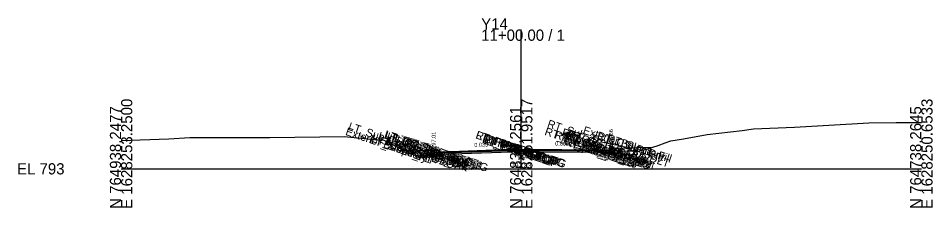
# Model space of a CAD drawing. Extents: x -26 to 1403, y -10 to 4517.
# Drawn here: x -25.7 to 202.8, y 1990.3 to 2037.5 of the extents above; entities that cross this region are included whole.
import ezdxf

# ---------------------------------------------------------------- set-up
doc = ezdxf.new("R2010")
doc.units = 0
for name, color, linetype in [('Default', 7, 'Continuous'), ('Exist CMT Pavement', 7, 'Continuous'), ('Exist Cross Section Cell', 7, 'Continuous'), ('Exist XS Center Line Elevation Label', 7, 'Continuous'), ('Exist XS Ground Line', 7, 'Continuous'), ('Prop CMT Conc Surface', 7, 'Continuous'), ('Prop CMT Concrete Structures', 7, 'Continuous'), ('Prop CMT Pvmt Course 1', 7, 'Continuous'), ('Prop CMT Pvmt Course 1 CG', 7, 'Continuous'), ('Prop CMT Pvmt Course 1 Wedge', 7, 'Continuous'), ('Prop CMT Pvmt Course 2', 7, 'Continuous'), ('Prop CMT Pvmt Course 2 Wedge', 7, 'Continuous'), ('Prop CMT Pvmt Course 3', 7, 'Continuous'), ('Prop CMT Pvmt Course 3 Wedge', 7, 'Continuous'), ('Prop CMT Pvmt Surface', 7, 'Continuous'), ('Prop CMT Pvmt Wedge Surface 1', 7, 'Continuous'), ('Prop CMT Pvmt Wedge Surface 2', 7, 'Continuous'), ('Prop CMT Pvmt Wedge Surface 3', 7, 'Continuous'), ('Prop CMT Slope Grass', 7, 'Continuous'), ('Prop CMT Subgrade Earthwork', 7, 'Continuous'), ('Prop XS Hydro Elevations', 7, 'Continuous'), ('Prop XS SE Text', 7, 'Continuous'), ('Scratch_Level_0', 7, 'Continuous')]:
    doc.layers.add(name, color=color, linetype=linetype)

msp = doc.modelspace()

# ---------------------------------------------------------------- linework, layer by layer
at = {"layer": 'Exist CMT Pavement'}
for points in [[(100, 2004.83), (96.42, 2004.84), (91.88, 2004.58), (80.18, 2003.95)], [(100, 2004.83), (80.18, 2003.95)], [(100, 2004.83), (104.2, 2004.83), (120.36, 2004.67)], [(100, 2004.83), (120.36, 2004.67)], [(120.36, 2004.67), (120.36, 2004.67)], [(80.18, 2003.95), (80.18, 2003.95)]]:
    msp.add_lwpolyline(points, dxfattribs=at)
at = {"layer": 'Exist Cross Section Cell'}
for p, q in [((100, 2000), (100, 2034.73)), ((0, 2000), (100, 2000)), ((100, 2000), (200, 2000))]:
    msp.add_line(p, q, dxfattribs=at)
at = {"layer": 'Exist XS Ground Line'}
msp.add_lwpolyline([(0, 2007.07), (11.97, 2007.49), (17.14, 2007.8), (31.71, 2007.81), (37.14, 2007.78), (49.67, 2007.98), (55.72, 2008.05), (64.16, 2007.23), (65.65, 2007.16), (67.35, 2006.31), (73.65, 2003.27), (75.02, 2003.31), (80.18, 2003.95), (91.88, 2004.58), (96.42, 2004.84), (100, 2004.83), (104.2, 2004.83), (120.36, 2004.67), (124.91, 2004.47), (129.26, 2004.42), (131.35, 2004.89), (134.23, 2005.81), (135.97, 2006.48), (137.35, 2006.96), (140.57, 2007.5), (146.51, 2008.53), (155.21, 2009.58), (158.09, 2009.99), (168.31, 2010.4), (186.85, 2011.47), (193.67, 2011.54), (200, 2011.58)], dxfattribs=at)
at = {"layer": 'Prop CMT Conc Surface'}
for points in [[(78.12, 2004.01), (78.11, 2004.51), (77.61, 2004.51)], [(120.43, 2004.75), (122.43, 2004.66)], [(122.43, 2004.66), (122.43, 2005.16), (122.93, 2005.16)], [(80.12, 2004.16), (78.12, 2004.01)]]:
    msp.add_lwpolyline(points, dxfattribs=at)
at = {"layer": 'Prop CMT Concrete Structures'}
for points in [[(80.12, 2004.16), (78.12, 2004.01), (78.11, 2004.51), (77.61, 2004.51)], [(77.61, 2004.51), (77.62, 2003.49), (80.12, 2003.58)], [(120.43, 2004.75), (122.43, 2004.66), (122.43, 2005.16), (122.93, 2005.16)], [(122.93, 2005.16), (122.93, 2004.16), (120.43, 2004.17)], [(120.43, 2004.17), (120.43, 2004.75)], [(80.12, 2003.58), (80.12, 2004.16)]]:
    msp.add_lwpolyline(points, dxfattribs=at)
at = {"layer": 'Prop CMT Pvmt Course 1'}
for points in [[(100, 2004.86), (80.12, 2004.16)], [(80.18, 2004.04), (100, 2004.73)], [(100, 2004.6), (100, 2004.86)], [(100, 2004.86), (120.43, 2004.75)], [(100, 2004.6), (100, 2004.86)], [(100, 2004.73), (100, 2004.6), (100, 2004.6)], [(120.36, 2004.63), (100, 2004.73)], [(100, 2004.73), (100, 2004.6), (100, 2004.6)], [(120.36, 2004.5), (120.36, 2004.63)], [(120.43, 2004.5), (120.36, 2004.5)], [(120.43, 2004.75), (120.43, 2004.5)], [(80.12, 2004.16), (80.12, 2003.91)], [(80.12, 2003.91), (80.18, 2003.91)], [(80.18, 2003.91), (80.18, 2004.04)]]:
    msp.add_lwpolyline(points, dxfattribs=at)
at = {"layer": 'Prop CMT Pvmt Course 1 CG'}
for points in [[(80.12, 2003.58), (77.12, 2003.47), (76.77, 2003.13)], [(76.77, 2003.13), (80.12, 2003.24)], [(80.12, 2003.24), (80.12, 2003.58)], [(120.43, 2004.17), (123.43, 2004.15), (123.76, 2003.82)], [(120.43, 2003.84), (120.43, 2004.17)], [(123.76, 2003.82), (120.43, 2003.84)]]:
    msp.add_lwpolyline(points, dxfattribs=at)
at = {"layer": 'Prop CMT Pvmt Course 1 Wedge'}
for points in [[(100, 2004.73), (80.18, 2004.04)], [(100, 2004.73), (120.36, 2004.63)]]:
    msp.add_lwpolyline(points, dxfattribs=at)
at = {"layer": 'Prop CMT Pvmt Course 2'}
for points in [[(120.36, 2004.17), (120.36, 2004.5)], [(120.36, 2004.5), (120.43, 2004.5)], [(120.43, 2004.5), (120.43, 2004.17)], [(80.18, 2003.91), (80.12, 2003.91)], [(80.12, 2003.91), (80.12, 2003.58)], [(80.12, 2003.58), (80.18, 2003.58)], [(80.18, 2003.58), (80.18, 2003.91)], [(120.43, 2004.17), (120.36, 2004.17)]]:
    msp.add_lwpolyline(points, dxfattribs=at)
at = {"layer": 'Prop CMT Pvmt Course 2 Wedge'}
for points in [[(100, 2004.6), (80.18, 2003.91)], [(100, 2004.6), (120.36, 2004.5)]]:
    msp.add_lwpolyline(points, dxfattribs=at)
at = {"layer": 'Prop CMT Pvmt Course 3'}
for points in [[(80.18, 2003.58), (80.12, 2003.58)], [(80.12, 2003.58), (80.12, 2003.24)], [(80.12, 2003.24), (80.18, 2003.24)], [(80.18, 2003.24), (80.18, 2003.58)], [(120.36, 2004.17), (120.43, 2004.17)], [(120.36, 2003.84), (120.36, 2004.17)], [(120.43, 2003.84), (120.36, 2003.84)], [(120.43, 2004.17), (120.43, 2003.84)]]:
    msp.add_lwpolyline(points, dxfattribs=at)
at = {"layer": 'Prop CMT Pvmt Course 3 Wedge'}
for points in [[(100, 2004.27), (80.18, 2003.58)], [(100, 2004.27), (120.36, 2004.17)]]:
    msp.add_lwpolyline(points, dxfattribs=at)
at = {"layer": 'Prop CMT Pvmt Surface'}
for points in [[(100, 2004.86), (80.12, 2004.16)], [(100, 2004.86), (120.43, 2004.75)]]:
    msp.add_lwpolyline(points, dxfattribs=at)
at = {"layer": 'Prop CMT Pvmt Wedge Surface 1'}
for points in [[(100, 2004.73), (80.18, 2004.04)], [(100, 2004.73), (120.36, 2004.63)], [(120.36, 2004.63), (120.36, 2004.5)], [(120.36, 2004.5), (120.43, 2004.5)], [(120.43, 2004.5), (120.43, 2004.75)], [(80.12, 2003.91), (80.12, 2004.16)], [(80.18, 2003.91), (80.12, 2003.91)], [(80.18, 2004.04), (80.18, 2003.91)]]:
    msp.add_lwpolyline(points, dxfattribs=at)
at = {"layer": 'Prop CMT Pvmt Wedge Surface 2'}
for points in [[(100, 2004.6), (80.12, 2003.91)], [(100, 2004.6), (120.43, 2004.5)], [(120.43, 2004.5), (120.43, 2004.75)], [(80.12, 2003.91), (80.12, 2004.16)]]:
    msp.add_lwpolyline(points, dxfattribs=at)
at = {"layer": 'Prop CMT Pvmt Wedge Surface 3'}
for points in [[(100, 2004.27), (80.12, 2003.58)], [(100, 2004.27), (120.43, 2004.17)], [(120.43, 2004.17), (120.43, 2004.75)], [(80.12, 2003.58), (80.12, 2004.16)]]:
    msp.add_lwpolyline(points, dxfattribs=at)
at = {"layer": 'Prop CMT Slope Grass'}
for points in [[(77.61, 2004.51), (70.8, 2004.65)], [(122.93, 2005.16), (132.82, 2005.36)]]:
    msp.add_lwpolyline(points, dxfattribs=at)
at = {"layer": 'Prop CMT Subgrade Earthwork'}
for points in [[(80.12, 2003.24), (76.77, 2003.13), (75.34, 2004.55)], [(120.36, 2003.84), (120.34, 2004.67)], [(120.43, 2003.84), (123.76, 2003.82), (125.15, 2005.21)], [(80.18, 2003.24), (80.12, 2003.24)], [(80.18, 2003.24), (80.2, 2003.95)], [(120.36, 2003.84), (120.43, 2003.84)]]:
    msp.add_lwpolyline(points, dxfattribs=at)

# ---------------------------------------------------------------- texts
at = {"layer": 'Default'}
msp.add_text('-', height=0.0001, dxfattribs=at).set_placement((0, 2000))
at = {"layer": 'Exist Cross Section Cell'}
for s, p in [('Y14', (90, 2034.73)), ('11+00.00 / 1', (90, 2031.93)), ('EL 793', (-26, 1998.6))]:
    msp.add_text(s, height=2.8, dxfattribs=at).set_placement(p)
for s, p in [('E 1628253.2500', (2.8, 1990)), ('E 1628251.9517', (102.8, 1990)), ('E 1628250.6533', (202.8, 1990)), ('N 764938.2477', (0, 1990)), ('N 764838.2561', (100, 1990)), ('N 764738.2645', (200, 1990))]:
    msp.add_text(s, height=2.8, rotation=90, dxfattribs=at).set_placement(p)
at = {"layer": 'Exist XS Center Line Elevation Label'}
msp.add_text('797.83', height=1.2, dxfattribs=at).set_placement((97.48, 2000.23))
at = {"layer": 'Prop XS Hydro Elevations'}
for s, p in [('797.01', (78.62, 2005.01)), ('797.66', (122.93, 2005.66))]:
    msp.add_text(s, height=1, rotation=90, dxfattribs=at).set_placement(p)
at = {"layer": 'Prop XS SE Text'}
for s, rotation, p in [('0.035', 2.0045, (88.29, 2005.45)), ('0.005', 359.7135, (108.48, 2005.81))]:
    msp.add_text(s, height=1, rotation=rotation, dxfattribs=at).set_placement(p)
at = {"layer": 'Scratch_Level_0'}
for s, p in [('LT_Sub_Trench_Out_DLT', (56.59, 2009.75)), ('RT_Sub_Trench_Out_DLT', (106.35, 2010.42)), ('Exterior Boundary', (55.92, 2008.48)), ('LT_PV_Sub_Tie_Out', (65.6, 2007.76)), ('LT_CG_Top_Face', (65.71, 2007.59)), ('LT_CG_Top_BOC', (66.18, 2007.27)), ('RT_PV_IEEOP_EG', (88.43, 2007.63)), ('LT_PV_IEEOP_EG', (88.48, 2007.62)), ('RT_PV_Sub_Tie_Out', (105.7, 2008.49)), ('RT_PV_OEEOP_EG', (108.18, 2007.67)), ('RT_CG_Top_Face', (109.98, 2008.26)), ('RT_CG1_Shelf_Out', (110.31, 2007.47)), ('RT_CG_Top_Gut', (110.9, 2007.45)), ('RT_CG_Top_BOC', (111.45, 2007.93)), ('Exterior Boundary', (115.26, 2008.79)), ('RT_CSLP_Pnt', (118.74, 2007.45)), ('LT_Slope_Fill', (61.98, 2006.46)), ('LT_CSLP_Pnt', (62.48, 2006.78)), ('LT_CG1_Shelf_Out', (64.04, 2006.77)), ('LT_CG_Bot_BOC', (66.21, 2006.23)), ('LT_CG_Top_Gut', (66.64, 2006.78)), ('LT_Sub_OEOP', (67.07, 2005.3)), ('LT_PV_OEEOP_EG', (68.05, 2006.94)), ('LT_Sub_OEEOP', (69.63, 2005.71)), ('LT_PV2_OEEOP', (69.72, 2006.34)), ('LT_PV3_OEEOP', (69.72, 2006.01)), ('LT_CG_Bot_IE', (70.23, 2005.82)), ('LT_PV1_OEEOP', (70.26, 2006.29)), ('LT_Sub_OEOT', (70.39, 2005.43)), ('LT_PV2_OEOT', (70.48, 2006.07)), ('LT_PV3_OEOT', (70.48, 2005.73)), ('LT_PV1_OEOT', (71.01, 2006.14)), ('RT_PV2_IEEOP', (90.11, 2006.85)), ('RT_PV3_IEEOP', (90.11, 2006.52)), ('LT_PV2_IEEOP', (90.15, 2006.83)), ('LT_PV3_IEEOP', (90.15, 2006.5)), ('RT_PV1_IEEOP', (90.65, 2006.79)), ('LT_PV1_IEEOP', (90.69, 2006.78)), ('PV2_PGL', (93.9, 2005.58)), ('PV1_PGL', (94.44, 2005.65)), ('RT_Sub_OEEOP', (109.76, 2006.31)), ('RT_PV2_OEEOP', (109.85, 2006.95)), ('RT_PV3_OEEOP', (109.85, 2006.62)), ('RT_PV1_OEEOP', (110.39, 2006.9)), ('RT_CG_Bot_IE', (110.5, 2006.43)), ('RT_Sub_OEOT', (110.65, 2006.04)), ('RT_PV2_OEOT', (110.74, 2006.68)), ('RT_PV3_OEOT', (110.74, 2006.34)), ('RT_PV1_OEOT', (111.28, 2006.75)), ('RT_CG_Bot_BOC', (111.48, 2006.92)), ('RT_Sub_OEOP', (114.02, 2006.01)), ('RT_Slope_Fill', (121.26, 2006.79))]:
    msp.add_text(s, height=2, rotation=341.5651, dxfattribs=at).set_placement(p)

doc.saveas('drawing.dxf')
